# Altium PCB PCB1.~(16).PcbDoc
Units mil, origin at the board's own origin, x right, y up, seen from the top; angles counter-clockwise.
Board outline 1890 x 1900 mil, 2 copper layers (Top Layer, Bottom Layer); 27 components, 29 nets, 115 pads, 18 vias.
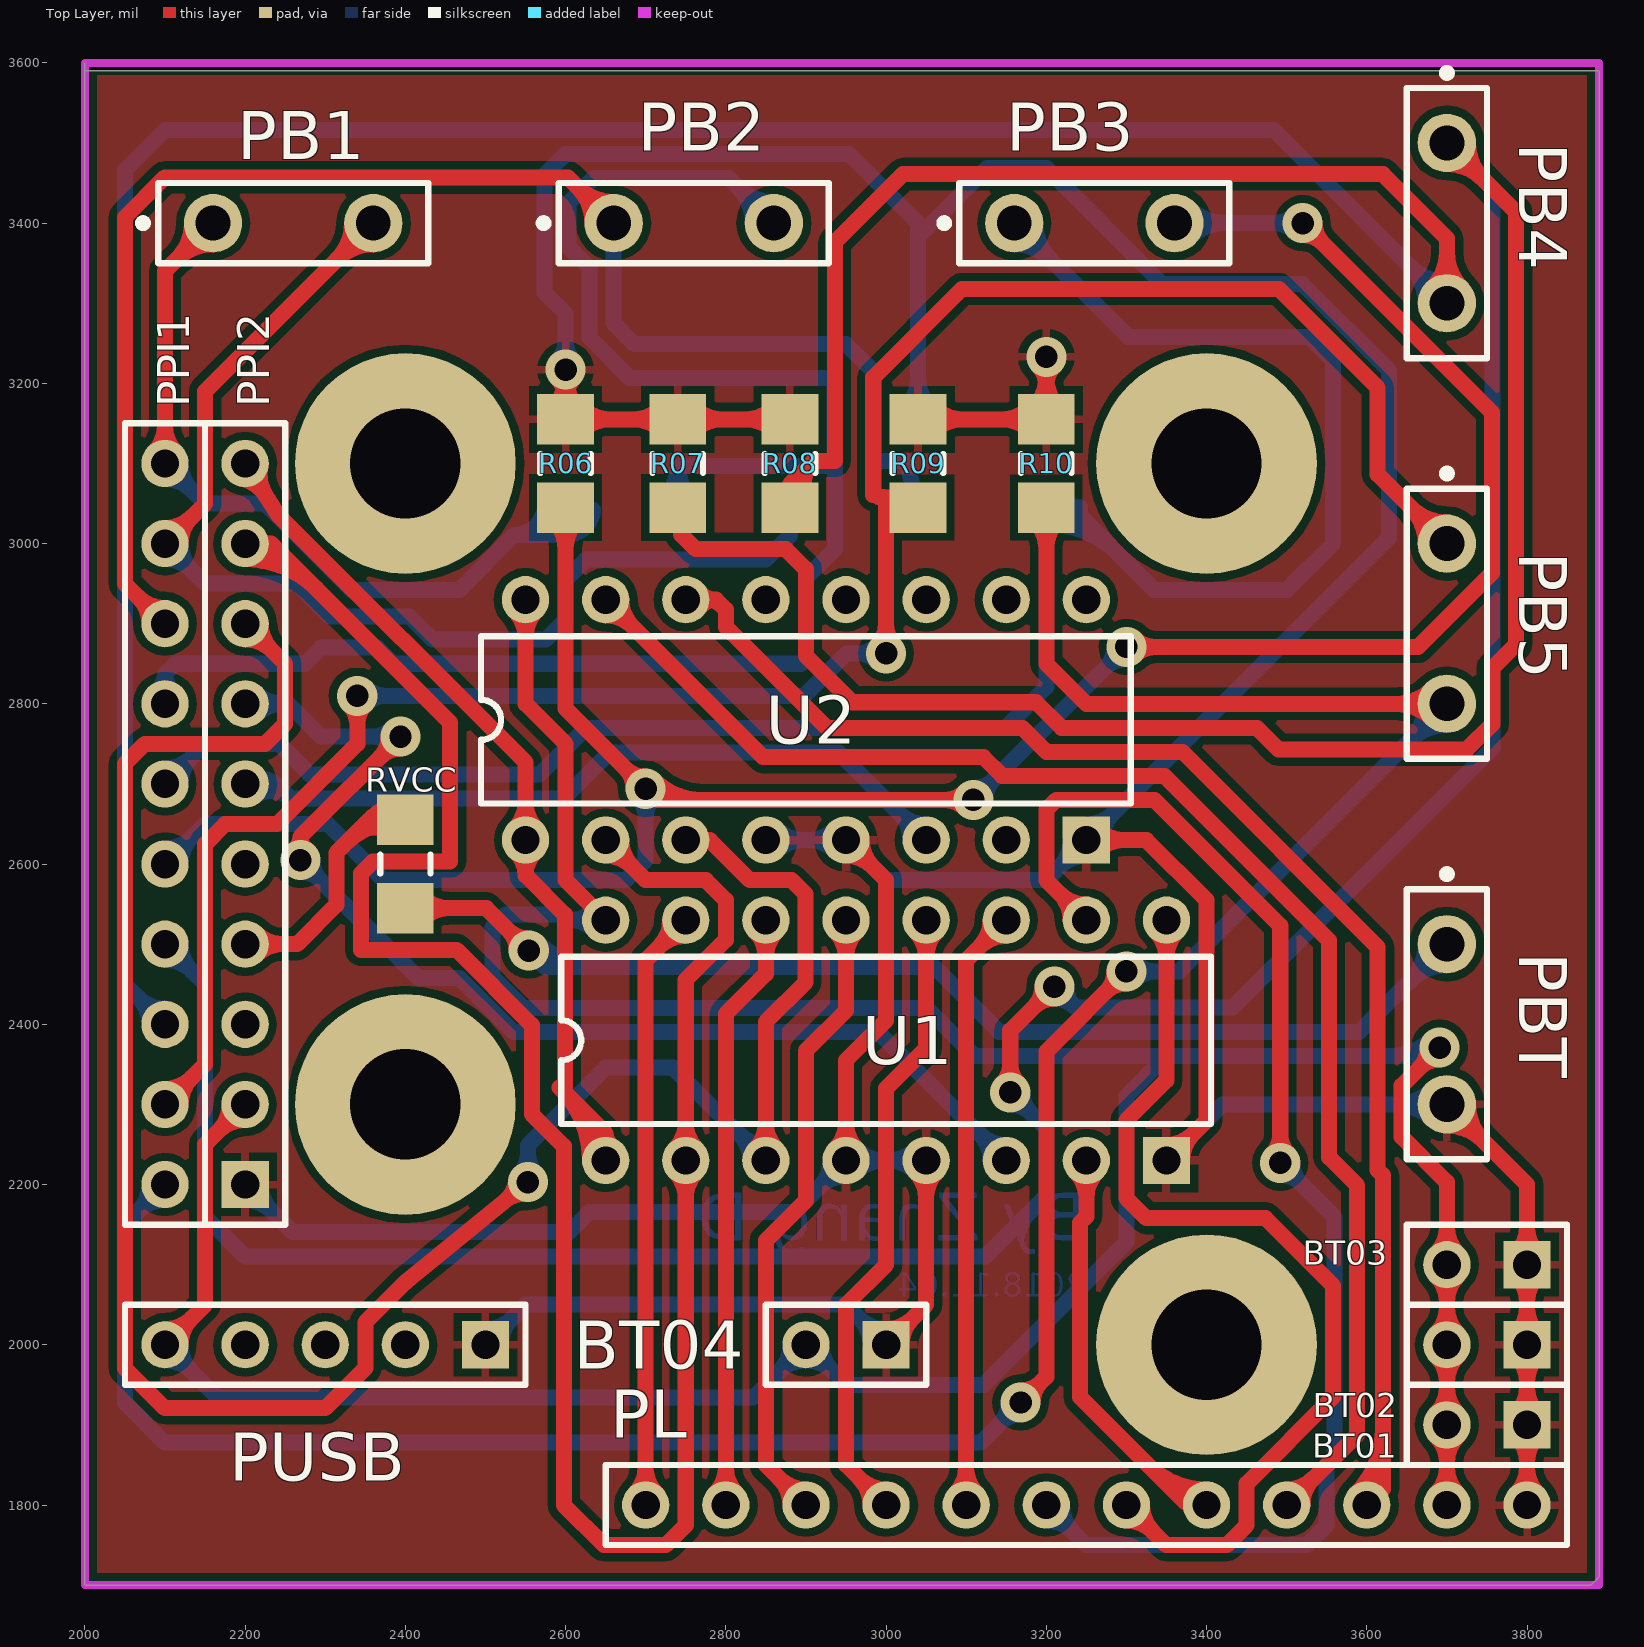
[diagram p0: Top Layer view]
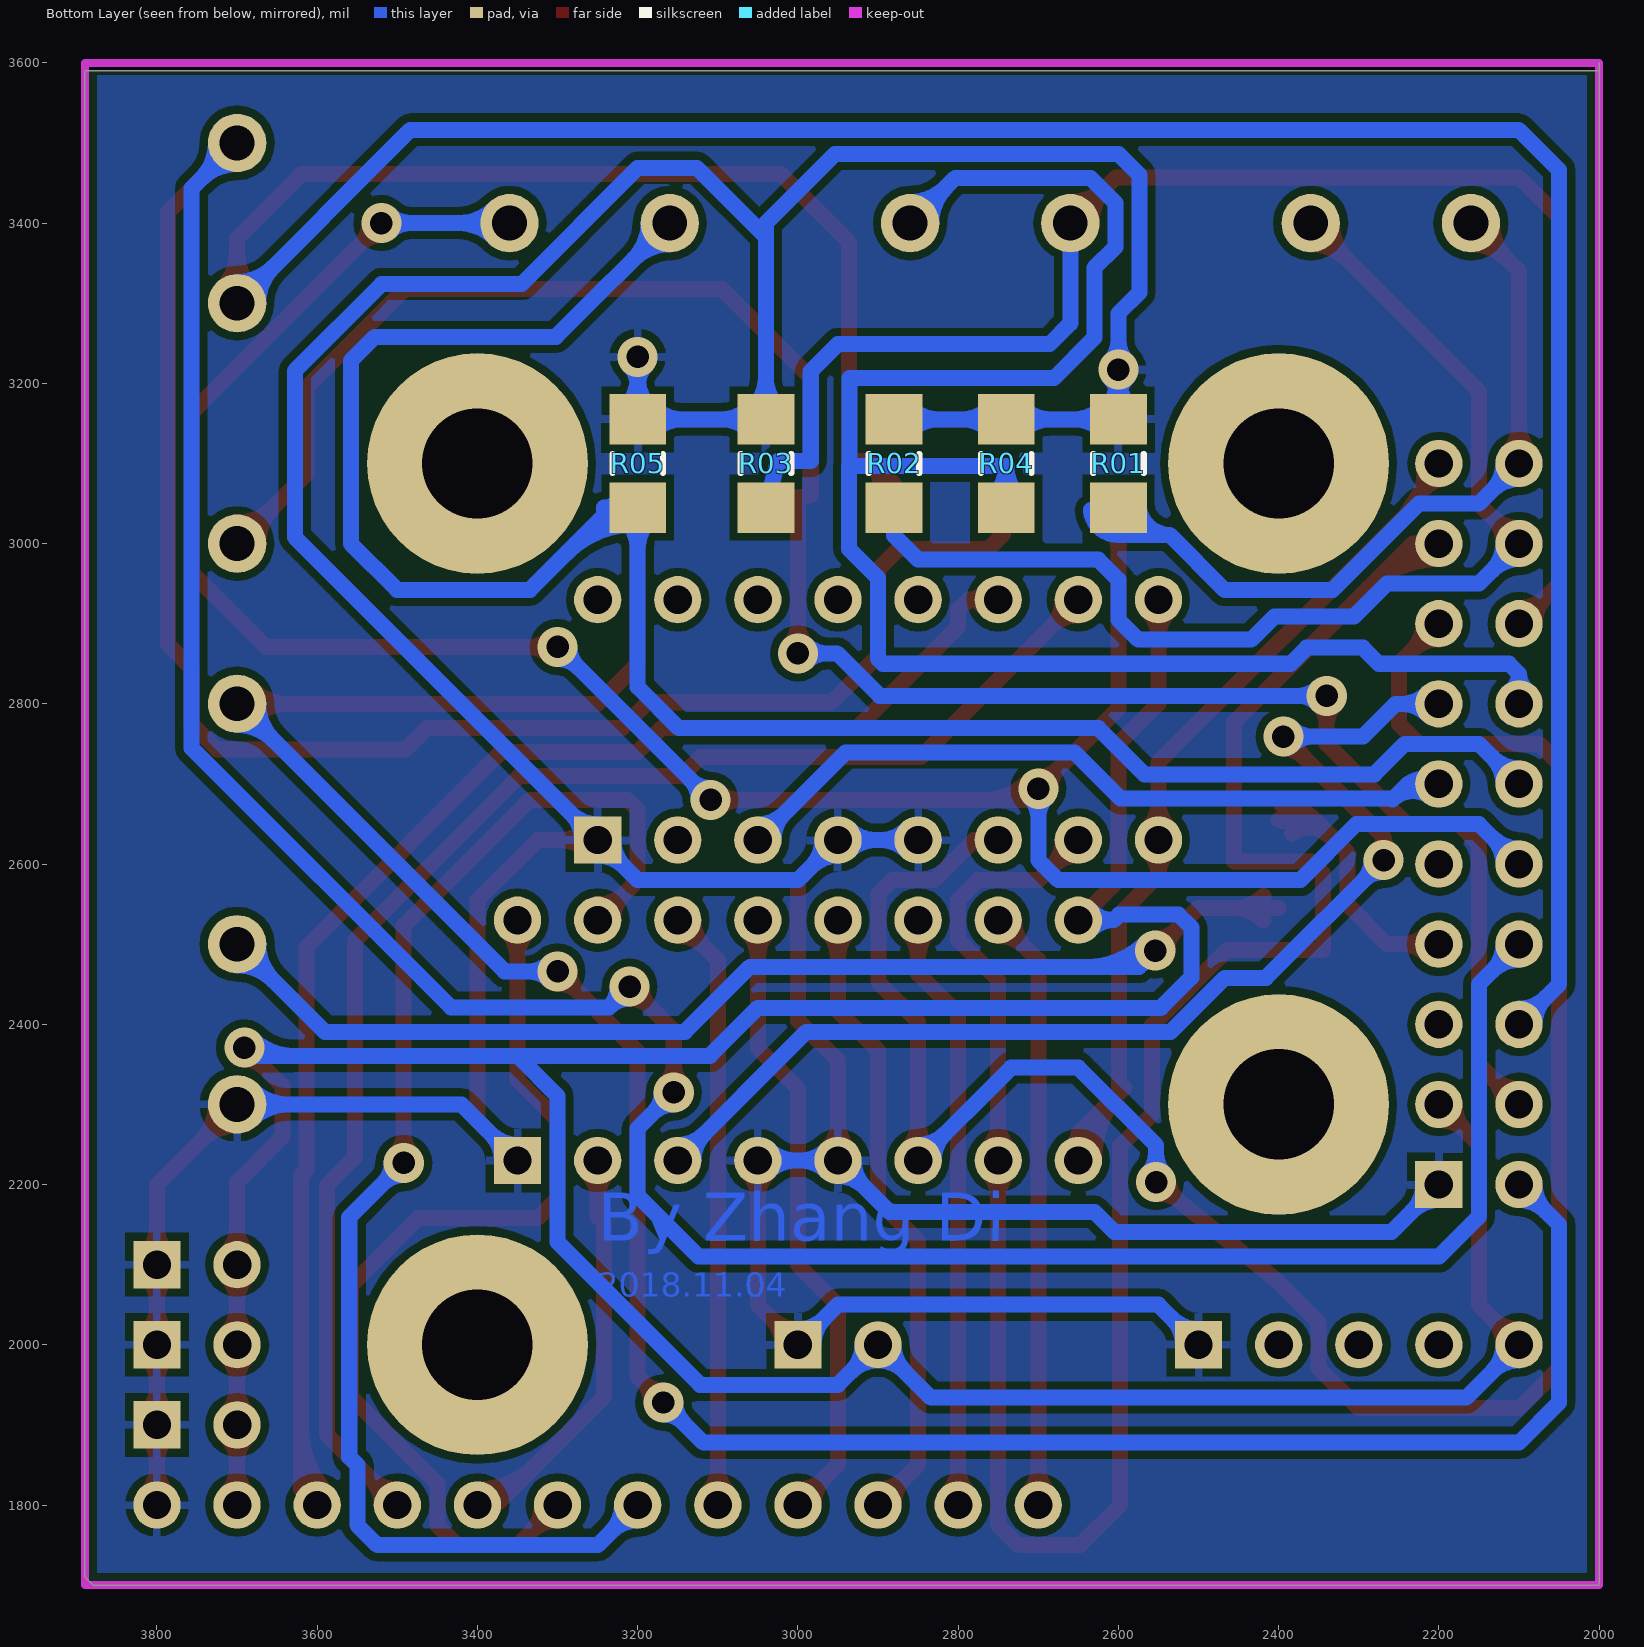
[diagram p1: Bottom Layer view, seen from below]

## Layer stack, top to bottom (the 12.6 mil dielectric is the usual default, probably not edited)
Top Layer: signal copper 1.4
Dielectric: dielectric 12.6, FR-4, Dk 4.8
Bottom Layer: signal copper 1.4

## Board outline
2010,3590 3890,3590 3890,1710 3880,1700 2000,1700 2000,3600 2000,3590

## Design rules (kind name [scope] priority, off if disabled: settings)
Clearance [All] p1: gap=10
ComponentClearance [All] p1: gap=10 collisioncheckmode=3 verticalgap=10
PolygonConnect [All] p1: connectstyle=Relief reliefconductorwidth=10 reliefentries=4 polygonreliefangle="90 Angle"
RoomDefinition Sheet1 [InComponentClass('Sheet1')] p1: confinementstyle=ConfineIn formatcopy=TRUE lockcomponents=FALSE outline 0,0 2000,0 2000,1000 0,1000
RoutingVias [All] p1: holewidth=28 width=50 viastyle="Through Hole" minholewidth=28 minwidth=50 maxholewidth=28 maxwidth=50
SolderMaskExpansion [All] p1: expansion=4
TestPointUsage [All] p1: valid=0 allowmultiple=FALSE
Testpoint [All] p1: side=15 testpointundercomponent=TRUE minsize=40 maxsize=100 preferedsize=60 minholesize=0 maxholesize=40 preferedholesize=32 testpointgrid=1 style=1023 order=0123456789
Width Width_2 [All] p1: maxlimit=30 minlimit=15 preferedwidth=20
Width Width_1 [InNet('VCC')] p2: maxlimit=30 minlimit=20 preferedwidth=30
Width [InNet('GND')] p3: maxlimit=30 minlimit=20 preferedwidth=30
18 further rules are at their usual default settings.

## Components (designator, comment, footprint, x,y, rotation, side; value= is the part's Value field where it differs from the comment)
BT01 "Header 2" HDR1X2 3800,1900 r180 top
BT02 "Header 2" HDR1X2 3800,2000 r180 top
BT03 "Header 2" HDR1X2 3800,2100 r180 top
BT04 "Header 2" HDR1X2 3000,2000 r180 top
PB1 "Header 2" SPST-2 2260,3400 r0 top
PB2 "Header 2" SPST-2 2760,3400 r0 top
PB3 "Header 2" SPST-2 3260,3400 r0 top
PB4 "Header 2" SPST-2 3700,3400 r270 top
PB5 "Header 2" SPST-2 3700,2900 r270 top
PBT "Header 2" SPST-2 3700,2400 r270 top
PL "Header 12" HDR1X12 2700,1800 r0 top
PPI1 "Header 10" HDR1X10#1 2100,3100 r270 top
PPI2 "Header 10" HDR1X10#2 2200,3100 r270 top
PUSB "Header 5" HDR1X5 2100,2000 r0 top
R01 "Res1" 3216[1206] 2600,3100 r270 bottom
R02 "Res1" 3216[1206] 2880,3100 r270 bottom
R03 "Res1" 3216[1206] 3040,3100 r270 bottom
R04 "Res1" 3216[1206] 2740,3100 r270 bottom
R05 "Res1" 3216[1206] 3200,3100 r270 bottom
R06 "Res1" 3216[1206] 2600,3100 r270 top
R07 "Res1" 3216[1206] 2740,3100 r270 top
R08 "Res1" 3216[1206] 2880,3100 r270 top
R09 "Res1" 3216[1206] 3040,3100 r270 top
R10 "Res1" 3216[1206] 3200,3100 r270 top
RVCC "Res1" 3216[1206] 2400,2600 r90 top
U1 "SN74HC138D" DIP-16 3000,2380 r0 top
U2 "SN74HC138D" DIP-16 2900,2780 r0 top

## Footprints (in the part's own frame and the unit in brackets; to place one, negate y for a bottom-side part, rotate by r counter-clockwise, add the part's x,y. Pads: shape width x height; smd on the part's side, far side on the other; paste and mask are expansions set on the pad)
3216[1206] [mm] "Chip Resistor; Body 3.2 x 1.6 mm (LxW typ)"
  rect 1.6x1.8 smd: 1(-1.4,0) 2(1.4,0)
  silkscreen extent -0.3,-0.8 0.3,0.8
DIP-16 [mm] "DIP; 16 Leads; Row Spacing 7.62 mm; Pitch 2.54 mm"
  round 1.5 hole 0.9: 1(-8.89,-3.81) 2(-6.35,-3.81) 3(-3.81,-3.81) 4(-1.27,-3.81) 5(1.27,-3.81) 6(3.81,-3.81) 7(6.35,-3.81) 9(8.89,3.81) 10(6.35,3.81) 11(3.81,3.81) 12(1.27,3.81) 13(-1.27,3.81) 14(-3.81,3.81) 15(-6.35,3.81) 16(-8.89,3.81)
  rect 1.5x1.5 hole 0.9: 8(8.89,-3.81)
  silkscreen extent -10.3,-2.65 10.3,2.65
HDR1X2 [mm] "Connector; Header; 2 Position"
  rect 1.5x1.5 hole 0.9: 1(0,0)
  round 1.5 hole 0.9: 2(2.54,0)
  silkscreen extent -1.27,-1.27 3.81,1.27
HDR1X5 [mm] "Connector; Header; 5 Position"
  round 1.5 hole 0.9: 1(0,0) 2(2.54,0) 3(5.08,0) 4(7.62,0)
  rect 1.5x1.5 hole 0.9: 5(10.16,0)
  silkscreen extent -1.27,-1.27 11.43,1.27
HDR1X10#1 [mm] "Connector; Header; 10 Position"
  round 1.5 hole 0.9: 1(0,0) 2(2.54,0) 3(5.08,0) 4(7.62,0) 5(10.16,0) 6(12.7,0) 7(15.24,0) 8(17.78,0) 9(20.32,0) 10(22.86,0)
  silkscreen extent -1.27,-1.27 24.13,1.27
HDR1X10#2 [mm] "Connector; Header; 10 Position"
  round 1.5 hole 0.9: 1(0,0) 2(2.54,0) 3(5.08,0) 4(7.62,0) 5(10.16,0) 6(12.7,0) 7(15.24,0) 8(17.78,0) 9(20.32,0)
  rect 1.5x1.5 hole 0.9: 10(22.86,0)
  silkscreen extent -1.27,-1.27 24.13,1.27
HDR1X12 [mm] "Connector; Header; 12 Position"
  round 1.5 hole 0.9: 1(0,0) 2(2.54,0) 3(5.08,0) 4(7.62,0) 5(10.16,0) 6(12.7,0) 7(15.24,0) 8(17.78,0) 9(20.32,0) 10(22.86,0) 11(25.4,0) 12(27.94,0)
  silkscreen extent -1.27,-1.27 29.21,1.27
SPST-2 [mm] "Circuit Breaker; 2 Leads"
  round 1.85 hole 1.1: 1(-2.54,0) 2(2.54,0)
  silkscreen extent -4.89,-1.27 4.28,1.27

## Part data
BT01 BT02 BT03 BT04 PB1 PB2 PB3 PB4 PB5 PBT: "Header, 2-Pin"
PL: "Header, 12-Pin"
PPI1 PPI2: "Header, 10-Pin"
PUSB: "Header, 5-Pin"
R01 R02 R03 R04 R05 R06 R07 R08 R09 R10 RVCC: "Resistor"
U1 U2: "3-Line to 8-Line Decoder / Demultiplexer"

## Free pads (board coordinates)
  round 275.59 hole 137.8: 0(3400,3100) 1(2400,3100) 3(3400,2000)
  round 275.59 hole 137.8 paste+0: 2(2400,2300)

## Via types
v1: diameter 50, hole 28, Top Layer to Bottom Layer, 18 vias

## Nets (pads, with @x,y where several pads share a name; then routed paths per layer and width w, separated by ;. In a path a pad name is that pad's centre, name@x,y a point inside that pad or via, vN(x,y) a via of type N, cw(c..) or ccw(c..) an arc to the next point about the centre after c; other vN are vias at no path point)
GND: BT01.1 BT02.1 BT03.1 BT04.1 PBT.2 PL.12 PPI2.10 PUSB.5 R01.1 R02.1 R03.1 R04.1 R05.1 R06.1 R07.1 R08.1 R09.1 R10.1 U1.4 U1.5 U1.8 U2.4 U2.5 U2.8 | length 11397.6
  Top Layer w20: R06.1@2584.8,3170.32 ccw(c2548.1,3207.01) 2600,3207.01 ccw(c2651.9,3207.01) R06.1@2615.2,3170.32 ; v1@2589.39,3206.39 cw(c2563.79,3180.79) 2600,3180.79 cw(c2636.21,3180.79) v1@2610.61,3206.39 ; v1(2600,3217) R06.1 R07.1 R08.1 ; R06.1@2619.14,3139.92 cw(c2655.83,3103.22) 2655.83,3155.12 cw(c2655.83,3207.01) R06.1@2619.14,3170.32 ; R07.1@2720.86,3139.92 ccw(c2684.17,3103.22) 2684.17,3155.12 ccw(c2684.17,3207.01) R07.1@2720.86,3170.32 ; R07.1@2759.14,3139.92 cw(c2795.83,3103.22) 2795.83,3155.12 cw(c2795.83,3207.01) R07.1@2759.14,3170.32 ; R08.1@2860.86,3139.92 ccw(c2824.17,3103.22) 2824.17,3155.12 ccw(c2824.17,3207.01) R08.1@2860.86,3170.32 ; U1.4@2936.19,2243.81 ccw(c2902.86,2277.14) 2950,2277.14 ccw(c2997.14,2277.14) U1.4@2963.81,2243.81 ; U1.4 2950,2355 3000,2405 3000,2580 U2.5 ; U2.5@2950,2610.47 cw(c2950,2563.33) 2983.34,2596.66 cw(c3016.67,2630) U2.5@2969.53,2630 ; BT04.1 3050,2050 U1.5 ; BT04.1@3000,2019.53 ccw(c3000,2066.67) 3033.34,2033.34 ccw(c3066.67,2000) BT04.1@3019.53,2000 ; U1.5@3036.19,2216.19 cw(c3002.86,2182.86) 3050,2182.86 cw(c3097.14,2182.86) U1.5@3063.81,2216.19 ; R09.1 R10.1 v1(3200,3233) ; R09.1@3059.14,3139.92 cw(c3095.83,3103.22) 3095.83,3155.12 cw(c3095.83,3207.01) R09.1@3059.14,3170.32 ; R10.1@3180.86,3139.92 ccw(c3144.17,3103.22) 3144.17,3155.12 ccw(c3144.17,3207.01) R10.1@3180.86,3170.32 ; R10.1@3184.8,3170.32 ccw(c3148.1,3207.01) 3200,3207.01 ccw(c3251.9,3207.01) R10.1@3215.2,3170.32 ; v1@3189.39,3222.39 cw(c3163.79,3196.79) 3200,3196.79 cw(c3236.21,3196.79) v1@3210.61,3222.39 ; U2.8 3325,2630 3400,2555 3400,2280 U1.8 ; U2.8@3263.81,2616.19 cw(c3297.14,2582.86) 3297.14,2630 cw(c3297.14,2677.14) U2.8@3263.81,2643.81 ; U1.8@3350,2249.53 ccw(c3350,2296.67) 3383.34,2263.34 ccw(c3416.67,2230) U1.8@3369.53,2230 ; PBT.2@3700,2273.58 cw(c3700,2209.81) 3745.1,2254.9 cw(c3790.19,2300) PBT.2@3726.42,2300 ; PBT.2 3800,2200 BT03.1 BT02.1 BT01.1 PL.12 ; PL.12@3786.19,1813.81 ccw(c3752.86,1847.14) 3800,1847.14 ccw(c3847.14,1847.14) PL.12@3813.81,1813.81 ; BT01.1@3786.19,1886.19 cw(c3752.86,1852.86) 3800,1852.86 cw(c3847.14,1852.86) BT01.1@3813.81,1886.19 ; BT01.1@3786.19,1913.81 ccw(c3752.86,1947.14) 3800,1947.14 ccw(c3847.14,1947.14) BT01.1@3813.81,1913.81 ; BT02.1@3786.19,1986.19 cw(c3752.86,1952.86) 3800,1952.86 cw(c3847.14,1952.86) BT02.1@3813.81,1986.19 ; BT02.1@3786.19,2013.81 ccw(c3752.86,2047.14) 3800,2047.14 ccw(c3847.14,2047.14) BT02.1@3813.81,2013.81 ; BT03.1@3786.19,2086.19 cw(c3752.86,2052.86) 3800,2052.86 cw(c3847.14,2052.86) BT03.1@3813.81,2086.19 ; BT03.1@3786.19,2113.81 ccw(c3752.86,2147.14) 3800,2147.14 ccw(c3847.14,2147.14) BT03.1@3813.81,2113.81
  Bottom Layer w20: PPI2.10@2200,2180.47 cw(c2200,2133.33) 2233.34,2166.66 cw(c2266.67,2200) PPI2.10@2219.53,2200 ; PPI2.10 2259,2141 2605,2141 2630,2166 2886,2166 U1.4 U1.5 ; PUSB.5 2550,2050 2950,2050 BT04.1 ; PUSB.5@2500,2019.53 ccw(c2500,2066.67) 2533.34,2033.34 ccw(c2566.67,2000) PUSB.5@2519.53,2000 ; R01.1@2584.8,3170.32 ccw(c2548.1,3207.01) 2600,3207.01 ccw(c2651.9,3207.01) R01.1@2615.2,3170.32 ; v1@2589.39,3206.39 cw(c2563.79,3180.79) 2600,3180.79 cw(c2636.21,3180.79) v1@2610.61,3206.39 ; v1@2589.39,3227.61 ccw(c2563.79,3253.21) 2600,3253.21 ccw(c2636.21,3253.21) v1@2610.61,3227.61 ; R01.1@2619.14,3139.92 cw(c2655.83,3103.22) 2655.83,3155.12 cw(c2655.83,3207.01) R01.1@2619.14,3170.32 ; R04.1@2720.86,3139.92 ccw(c2684.17,3103.22) 2684.17,3155.12 ccw(c2684.17,3207.01) R04.1@2720.86,3170.32 ; R04.1@2759.14,3139.92 cw(c2795.83,3103.22) 2795.83,3155.12 cw(c2795.83,3207.01) R04.1@2759.14,3170.32 ; U2.4 U2.5 3000,2580 3200,2580 U2.8 3628,3008 3628,3215.5 3519.5,3324 3345,3324 3200,3469 3126,3469 3040,3383 ; R02.1@2860.86,3139.92 ccw(c2824.17,3103.22) 2824.17,3155.12 ccw(c2824.17,3207.01) R02.1@2860.86,3170.32 ; U2.4@2863.81,2616.19 cw(c2897.14,2582.86) 2897.14,2630 cw(c2897.14,2677.14) U2.4@2863.81,2643.81 ; R02.1 R04.1 R01.1 v1(2600,3217) 2600,3287.16 2573.58,3313.58 2573.58,3460 2600,3486.42 2953.58,3486.42 3040,3400 3040,3383 ; U1.4@2930.47,2230 cw(c2883.33,2230) 2916.66,2196.66 cw(c2950,2163.33) U1.4@2950,2210.47 ; U2.5@2936.19,2616.19 ccw(c2902.86,2582.86) 2902.86,2630 ccw(c2902.86,2677.14) U2.5@2936.19,2643.81 ; U2.5@2950,2610.47 cw(c2950,2563.33) 2983.34,2596.66 cw(c3016.67,2630) U2.5@2969.53,2630 ; U1.4@2963.81,2216.19 cw(c2997.14,2182.86) 2997.14,2230 cw(c2997.14,2277.14) U1.4@2963.81,2243.81 ; BT04.1@2980.47,2000 ccw(c2933.33,2000) 2966.66,2033.34 ccw(c3000,2066.67) BT04.1@3000,2019.53 ; R03.1@3024.8,3170.32 ccw(c2988.1,3207.01) 3040,3207.01 ccw(c3091.9,3207.01) R03.1@3055.2,3170.32 ; U1.5@3036.19,2216.19 ccw(c3002.86,2182.86) 3002.86,2230 ccw(c3002.86,2277.14) U1.5@3036.19,2243.81 ; R03.1@3059.14,3139.92 cw(c3095.83,3103.22) 3095.83,3155.12 cw(c3095.83,3207.01) R03.1@3059.14,3170.32 ; R05.1@3180.86,3139.92 ccw(c3144.17,3103.22) 3144.17,3155.12 ccw(c3144.17,3207.01) R05.1@3180.86,3170.32 ; R05.1@3184.8,3170.32 ccw(c3148.1,3207.01) 3200,3207.01 ccw(c3251.9,3207.01) R05.1@3215.2,3170.32 ; v1@3189.39,3222.39 cw(c3163.79,3196.79) 3200,3196.79 cw(c3236.21,3196.79) v1@3210.61,3222.39 ; v1(3200,3233) R05.1 R03.1 3040,3383 ; U2.8@3230.47,2630 cw(c3183.33,2630) 3216.66,2596.66 cw(c3250,2563.33) U2.8@3250,2610.47 ; U2.8@3250,2649.53 ccw(c3250,2696.67) 3283.34,2663.34 ccw(c3316.67,2630) U2.8@3269.53,2630 ; U1.8 3420,2300 PBT.2 ; U1.8@3350,2249.53 ccw(c3350,2296.67) 3383.34,2263.34 ccw(c3416.67,2230) U1.8@3369.53,2230 ; PBT.2@3681.32,2281.32 ccw(c3636.22,2236.22) 3636.22,2300 ccw(c3636.22,2363.78) PBT.2@3681.32,2318.68
NetPB1_1: PB1.1 PPI1.1 R01.2 | length 1416.3
  Top Layer w20: PPI1.1@2086.19,3113.81 ccw(c2052.86,3147.14) 2100,3147.14 ccw(c2147.14,3147.14) PPI1.1@2113.81,3113.81 ; PPI1.1 2100,3340 PB1.1 ; PB1.1@2133.58,3400 cw(c2069.81,3400) 2114.9,3354.9 cw(c2160,3309.81) PB1.1@2160,3373.58
  Bottom Layer w20: PPI1.1@2100,3080.47 cw(c2100,3033.33) 2133.34,3066.66 cw(c2166.67,3100) PPI1.1@2119.53,3100 ; PPI1.1 2150,3050 2225,3050 2333,2942 2467,2942 2536,3011 ; 2557.69,3011 ccw(c2557.69,3048) R01.2@2594.57,3045 ; R01.2@2574.64,3046.62 cw(c2536,3049.76) 2536,3011 ; 2579.38,3011 ccw(c2579.38,3046.24) R01.2@2614.51,3043.38 ; R01.2 2600,3011 2536,3011 ; 2601.08,3011 ccw(c2601.08,3044.47) R01.2@2634.44,3041.76
NetPB1_2: PB1.2 PPI1.2 R02.2 | length 1703.7
  Top Layer w20: PPI1.2 2150,3050 2150,3190 PB1.2 ; PPI1.2@2100,3019.53 ccw(c2100,3066.67) 2133.34,3033.34 ccw(c2166.67,3000) PPI1.2@2119.53,3000 ; PB1.2@2333.58,3400 cw(c2269.81,3400) 2314.9,3354.9 cw(c2360,3309.81) PB1.2@2360,3373.58
  Bottom Layer w20: PPI1.2@2100,2980.47 cw(c2100,2933.33) 2133.34,2966.66 cw(c2166.67,3000) PPI1.2@2119.53,3000 ; PPI1.2 2150,2950 2264.98,2950 2306.05,2908.93 2405.3,2908.93 2434.23,2880 2575,2880 2600,2905 2600,2955 2625,2980 2850,2980 2880,3010 R02.2
NetPB2_1: PB2.1 PPI1.3 R03.2 | length 2043.1
  Top Layer w20: PPI1.3@2080.47,2900 ccw(c2033.33,2900) 2066.66,2933.34 ccw(c2100,2966.67) PPI1.3@2100,2919.53 ; PPI1.3 2050,2950 2050,3407 2100,3457 2603,3457 PB2.1 ; PB2.1@2633.58,3400 ccw(c2569.81,3400) 2614.9,3445.1 ccw(c2660,3490.19) PB2.1@2660,3426.42
  Bottom Layer w20: PB2.1 2660,3275 2686,3249 2950,3249 2984,3215 2984,3103 3025,3103 R03.2
NetPB2_2: PB2.2 PPI1.4 R04.2 | length 2505.4
  Bottom Layer w20: PPI1.4@2088.8,2816 ccw(c2073.76,2837.5) 2100,2837.5 ; PPI1.4 2100,2837.5 ; PPI1.4@2111.2,2816 cw(c2126.24,2837.5) 2100,2837.5 ; R04.2@2724.8,3060.08 ccw(c2688.1,3096.78) 2740,3096.78 ccw(c2791.9,3096.78) R04.2@2755.2,3060.08 ; R04.2 2740,3097 2935.44,3097 ; PB2.2@2833.58,3400 ccw(c2769.81,3400) 2814.9,3445.1 ccw(c2860,3490.19) PB2.2@2860,3426.42 ; PB2.2 2803.58,3456.42 2635,3456.42 2603.58,3425 2603.58,3370.42 2630,3344 2630,3257 2680.38,3206.62 2935.44,3206.62 2935.44,3097 ; 2100,2837.5 2112.5,2850 2275,2850 2295,2870 2365,2870 2385,2850 2893.74,2850 2900,2856.26 2900,2957 2936,2993 2936,3097 2935.44,3097
NetPB3_1: PB3.1 PPI1.5 R05.2 | length 3067.5
  Bottom Layer w20: PPI1.5 2150,2750 2242.5,2750 2280.5,2712 2567.47,2712 2625,2769.53 3148.53,2769.53 3200,2821 R05.2 3242.2,3044.88 ; PPI1.5@2100,2719.53 ccw(c2100,2766.67) 2133.34,2733.34 ccw(c2166.67,2700) PPI1.5@2119.53,2700 ; PB3.1@3160,3373.58 cw(c3160,3309.81) 3205.1,3354.9 cw(c3250.19,3400) PB3.1@3186.42,3400 ; PB3.1 3302,3258 3528,3258 3558,3228 3558,3000 3500.2,2942.2 3334.64,2942.2 3242.2,3034.64 3242.2,3044.88 ; R05.2@3184.8,3029.68 cw(c3148.1,2992.99) 3200,2992.99 cw(c3251.9,2992.99) R05.2@3215.2,3029.68 ; R05.2@3203.94,3023.39 cw(c3203.94,2903.84) 3288.47,2988.37 ; R05.2@3203.94,3043.39 cw(c3203.94,2972.12) 3254.33,3022.51 ; R05.2@3204.68,3043.58 cw(c3218.28,3019.75) 3237.69,3039.15 ; R05.2@3214.59,3026.21 cw(c3231.75,2996.16) 3256.21,3020.63 ; R05.2@3222.29,3033.7 cw(c3242.2,3021.57) 3242.2,3044.88 ; R05.2@3222.29,3056.07 ccw(c3242.2,3068.19) 3242.2,3044.88
NetPB3_2: PB3.2 PPI1.6 R06.2 | length 3820.4
  Top Layer w20: R06.2@2584.8,3029.68 cw(c2548.1,2992.99) 2600,2992.99 cw(c2651.9,2992.99) R06.2@2615.2,3029.68 ; R06.2 2600,2794 v1(2700,2694) 2714,2680 v1(3109,2680) ; v1@2685,2694 ccw(c2648.79,2694) 2674.39,2719.61 ccw(c2700,2745.21) v1@2700,2709 ; v1@2696.46,2690.46 ccw(c2721.73,2715.73) 2721.73,2680 ; v1@2710.61,2704.61 ccw(c2770.01,2764.01) 2770.01,2680 ; v1@3098.39,2669.39 ccw(c3072.79,2643.79) 3072.79,2680 ccw(c3072.79,2716.21) v1@3098.39,2690.61 ; v1(3300,2871) 3664,2871 3756.42,2963.42 3756.42,3163.58 v1(3520,3400) ; v1@3310.61,2860.39 cw(c3336.21,2834.79) 3336.21,2871 cw(c3336.21,2907.21) v1@3310.61,2881.61 ; v1@3520,3385 cw(c3520,3348.79) 3545.61,3374.39 cw(c3571.21,3400) v1@3535,3400
  Bottom Layer w20: PPI1.6 2150,2650 2303,2650 2373,2580 2675,2580 2700,2605 v1(2700,2694) ; PPI1.6@2100,2619.53 ccw(c2100,2666.67) 2133.34,2633.34 ccw(c2166.67,2600) PPI1.6@2119.53,2600 ; v1@2689.39,2683.39 cw(c2663.79,2657.79) 2700,2657.79 cw(c2736.21,2657.79) v1@2710.61,2683.39 ; v1(3109,2680) v1(3300,2871) ; v1@3109,2695 ccw(c3109,2731.21) 3134.61,2705.61 ccw(c3160.21,2680) v1@3124,2680 ; v1@3285,2871 cw(c3248.79,2871) 3274.39,2845.39 cw(c3300,2819.79) v1@3300,2856 ; PB3.2 v1(3520,3400) ; PB3.2@3378.68,3381.32 cw(c3423.78,3336.22) 3423.78,3400 cw(c3423.78,3463.78) PB3.2@3378.68,3418.68 ; v1@3509.39,3389.39 ccw(c3483.79,3363.79) 3483.79,3400 ccw(c3483.79,3436.21) v1@3509.39,3410.61
NetPB4_1: PB4.1 PPI1.7 R07.2 | length 5783.7
  Top Layer w20: R07.2@2735.1,3025.29 cw(c2728.87,3011.5) 2744,3011.5 ; R07.2 2744,3044.88 2744,3011.5 ; R07.2@2752.88,3025.34 ccw(c2759.22,3011.5) 2744,3011.5 ; v1@3144.39,2325.61 ccw(c3118.79,2351.21) 3155,2351.21 ccw(c3191.21,2351.21) v1@3165.61,2325.61 ; v1(3155,2315) 3155,2392 v1(3210,2447) ; v1@3195,2447 cw(c3158.79,2447) 3184.39,2421.39 cw(c3210,2395.79) v1@3210,2432 ; PB4.1@3700,3473.58 cw(c3700,3409.81) 3745.1,3454.9 cw(c3790.19,3500) PB4.1@3726.42,3500 ; PB4.1 3786.42,3413.58 3786.42,2874.48 3757,2845.06 3757,2775 3725,2743 3489.71,2743 3462.71,2770 3219.08,2770 3187.13,2801.95 2958.05,2801.95 2900,2860 2900,2968 2875,2993 2762.5,2993 2744,3011.5
  Bottom Layer w20: PPI1.7@2100,2480.47 cw(c2100,2433.33) 2133.34,2466.66 cw(c2166.67,2500) PPI1.7@2119.53,2500 ; PPI1.7 2150,2450 2150,2160 2200,2110 3124,2110 3200,2186 3200,2270 v1(3155,2315) ; v1@3155,2300 cw(c3155,2263.79) 3180.61,2289.39 cw(c3206.21,2315) v1@3170,2315 ; v1@3210,2432 cw(c3210,2395.79) 3235.61,2421.39 cw(c3261.21,2447) v1@3225,2447 ; v1(3210,2447) 3236,2421 3433,2421 3757,2745 3757,3443 PB4.1 ; PB4.1@3700,3473.58 cw(c3700,3409.81) 3745.1,3454.9 cw(c3790.19,3500) PB4.1@3726.42,3500
NetPB4_2: PB4.2 PPI1.8 R08.2 | length 4498.7
  Top Layer w20: R08.2 2880,3074 2909,3103 ; R08.2@2885.24,3045.62 cw(c2913.3,3061.62) 2890.46,3084.46 ; R08.2@2902.61,3055.53 cw(c2936.92,3075.08) 2909,3103 ; PB4.2@3681.32,3318.68 ccw(c3636.22,3363.78) 3700,3363.78 ccw(c3763.78,3363.78) PB4.2@3718.68,3318.68 ; PB4.2 3700,3381 3620,3461 3021,3461 2936,3376 2936,3103 2909,3103
  Bottom Layer w20: PPI1.8@2080.47,2400 ccw(c2033.33,2400) 2066.66,2433.34 ccw(c2100,2466.67) PPI1.8@2100,2419.53 ; PPI1.8 2050,2450 2050,3466 2100.42,3516.42 3483.58,3516.42 PB4.2 ; PB4.2@3673.58,3300 ccw(c3609.81,3300) 3654.9,3345.1 ccw(c3700,3390.19) PB4.2@3700,3326.42
NetPB5_1: PB5.1 PPI1.9 R09.2 | length 3237.7
  Top Layer w20: PPI1.9 2150,2350 2150,2625 2175,2650 2240,2650 2340,2750 v1(2340,2810) ; PPI1.9@2100,2319.53 ccw(c2100,2366.67) 2133.34,2333.34 ccw(c2166.67,2300) PPI1.9@2119.53,2300 ; v1@2329.39,2799.39 cw(c2303.79,2773.79) 2340,2773.79 cw(c2376.21,2773.79) v1@2350.61,2799.39 ; 2983.95,3060.9 cw(c2968.68,3007.45) R09.2@3017.27,3034.44 ; 2988.97,3059.46 ccw(c3002.21,3105.81) R09.2@3025.62,3063.67 ; v1@2989.39,2873.61 ccw(c2963.79,2899.21) 3000,2899.21 ccw(c3036.21,2899.21) v1@3010.61,2873.61 ; v1(3000,2863) 3000,3044.88 ; R09.2@3017.15,3034.66 ccw(c3000,3025.38) 3000,3044.88 ; R09.2@3017.15,3055.11 cw(c3000,3064.38) 3000,3044.88 ; PB5.1@3673.58,3000 ccw(c3609.81,3000) 3654.9,3045.1 ccw(c3700,3090.19) PB5.1@3700,3026.42 ; PB5.1 3613.58,3086.42 3613.58,3194.42 3490.2,3317.8 3094.8,3317.8 2984,3207 2984,3060.88 R09.2 3000,3044.88
  Bottom Layer w20: v1(2340,2810) 2898,2810 2951,2863 v1(3000,2863) ; v1@2350.61,2799.39 cw(c2376.21,2773.79) 2376.21,2810 cw(c2376.21,2846.21) v1@2350.61,2820.61 ; v1@2989.39,2852.39 ccw(c2963.79,2826.79) 2963.79,2863 ccw(c2963.79,2899.21) v1@2989.39,2873.61
NetPB5_2: PB5.2 PPI1.10 R10.2 | length 3882.2
  Top Layer w20: v1(3168,1928) 3200,1960 3200,2366 v1(3300,2466) ; v1@3168,1943 ccw(c3168,1979.21) 3193.61,1953.61 ccw(c3219.21,1928) v1@3183,1928 ; R10.2@3184.8,3029.68 cw(c3148.1,2992.99) 3200,2992.99 cw(c3251.9,2992.99) R10.2@3215.2,3029.68 ; R10.2 3200,2850 3250,2800 PB5.2 ; v1@3285,2466 cw(c3248.79,2466) 3274.39,2440.39 cw(c3300,2414.79) v1@3300,2451 ; PB5.2@3681.32,2781.32 ccw(c3636.22,2736.22) 3636.22,2800 ccw(c3636.22,2863.78) PB5.2@3681.32,2818.68
  Bottom Layer w20: PPI1.10@2080.47,2200 cw(c2033.33,2200) 2066.66,2166.66 cw(c2100,2133.33) PPI1.10@2100,2180.47 ; PPI1.10 2050,2150 2050,1928 2100,1878 3118,1878 v1(3168,1928) ; v1@3153,1928 cw(c3116.79,1928) 3142.39,1902.39 cw(c3168,1876.79) v1@3168,1913 ; v1(3300,2466) 3366,2466 PB5.2 ; v1@3310.61,2455.39 cw(c3336.21,2429.79) 3336.21,2466 cw(c3336.21,2502.21) v1@3310.61,2476.61 ; PB5.2@3673.58,2800 cw(c3609.81,2800) 3654.9,2754.9 cw(c3700,2709.81) PB5.2@3700,2773.58
NetPBT_1: PBT.1 RVCC.1 | length 1776.3
  Top Layer w20: RVCC.1 2501.12,2544.88 v1(2554,2492) ; RVCC.1@2419.14,2529.68 cw(c2455.83,2492.99) 2455.83,2544.88 cw(c2455.83,2596.78) RVCC.1@2419.14,2560.08 ; v1@2539,2492 ccw(c2502.79,2492) 2528.39,2517.61 ccw(c2554,2543.21) v1@2554,2507
  Bottom Layer w20: v1@2550.46,2488.46 ccw(c2591.19,2529.19) 2591.19,2471.59 ; v1(2554,2492) 2574.41,2471.59 3060.09,2471.59 3141.21,2390.47 3590.47,2390.47 PBT.1 ; v1@2564.61,2502.61 ccw(c2639.48,2577.48) 2639.48,2471.59 ; PBT.1@3673.58,2500 cw(c3609.81,2500) 3654.9,2454.9 cw(c3700,2409.81) PBT.1@3700,2473.58
NetPL_1: PL.1 U1.15 | length 898.8
  Top Layer w20: PL.1@2686.19,1813.81 ccw(c2652.86,1847.14) 2700,1847.14 ccw(c2747.14,1847.14) PL.1@2713.81,1813.81 ; PL.1 2700,2480 U1.15 ; U1.15@2730.47,2530 cw(c2683.33,2530) 2716.66,2496.66 cw(c2750,2463.33) U1.15@2750,2510.47
NetPL_2: PL.2 U1.14 | length 898.8
  Top Layer w20: PL.2@2786.19,1813.81 ccw(c2752.86,1847.14) 2800,1847.14 ccw(c2847.14,1847.14) PL.2@2813.81,1813.81 ; PL.2 2800,2413 2850,2463 U1.14 ; U1.14@2836.19,2516.19 cw(c2802.86,2482.86) 2850,2482.86 cw(c2897.14,2482.86) U1.14@2863.81,2516.19
NetPL_3: PL.3 U1.13 | length 940.2
  Top Layer w20: PL.3@2880.47,1800 ccw(c2833.33,1800) 2866.66,1833.34 ccw(c2900,1866.67) PL.3@2900,1819.53 ; PL.3 2850,1850 2850,2130 2900,2180 2900,2367 2950,2417 U1.13 ; U1.13@2936.19,2516.19 cw(c2902.86,2482.86) 2950,2482.86 cw(c2997.14,2482.86) U1.13@2963.81,2516.19
NetPL_4: PL.4 U1.12 | length 940.2
  Top Layer w20: PL.4@2980.47,1800 ccw(c2933.33,1800) 2966.66,1833.34 ccw(c3000,1866.67) PL.4@3000,1819.53 ; PL.4 2950,1850 2950,2050 3000,2100 3000,2320 3050,2370 U1.12 ; U1.12@3036.19,2516.19 cw(c3002.86,2482.86) 3050,2482.86 cw(c3097.14,2482.86) U1.12@3063.81,2516.19
NetPL_5: PL.5 U1.11 | length 898.8
  Top Layer w20: PL.5@3086.19,1813.81 ccw(c3052.86,1847.14) 3100,1847.14 ccw(c3147.14,1847.14) PL.5@3113.81,1813.81 ; PL.5 3100,2480 U1.11 ; U1.11@3130.47,2530 cw(c3083.33,2530) 3116.66,2496.66 cw(c3150,2463.33) U1.11@3150,2510.47
NetPL_6: PL.6 U1.10 | length 1943.7
  Top Layer w20: U1.10@3230.47,2530 ccw(c3183.33,2530) 3216.66,2563.34 ccw(c3250,2596.67) U1.10@3250,2549.53 ; U1.10 3200,2580 3200,2667.5 3212.5,2680 3335,2680 3492,2523 v1(3492,2227) ; v1@3481.39,2237.61 ccw(c3455.79,2263.21) 3492,2263.21 ccw(c3528.21,2263.21) v1@3502.61,2237.61
  Bottom Layer w20: PL.6@3200,1780.47 cw(c3200,1733.33) 3233.34,1766.66 cw(c3266.67,1800) PL.6@3219.53,1800 ; PL.6 3250,1750 3525,1750 3550,1775 3550,1850 3560,1860 3560,2159 v1(3492,2227) ; v1@3492,2212 cw(c3492,2175.79) 3517.61,2201.39 cw(c3543.21,2227) v1@3507,2227
NetPL_7: PL.7 U1.9 | length 1343.5
  Top Layer w20: PL.7@3300,1780.47 cw(c3300,1733.33) 3333.34,1766.66 cw(c3366.67,1800) PL.7@3319.53,1800 ; PL.7 3350,1750 3425,1750 3450,1775 3450,1826.84 3558,1934.84 3558,2073.6 3473.6,2158 3325,2158 3300,2183 3300,2280 3350,2330 U1.9 ; U1.9@3336.19,2516.19 cw(c3302.86,2482.86) 3350,2482.86 cw(c3397.14,2482.86) U1.9@3363.81,2516.19
NetPL_8: PL.8 U1.7 | length 712.7
  Top Layer w20: U1.7@3236.19,2216.19 cw(c3202.86,2182.86) 3250,2182.86 cw(c3297.14,2182.86) U1.7@3263.81,2216.19 ; U1.7 3250,2160 3242,2152 3242,1934.84 3372.84,1804 3400,1804 PL.8 ; 3327.13,1849.71 ccw(c3400,1922.58) PL.8@3400,1819.53 ; 3361.27,1815.57 ccw(c3400,1854.3) PL.8@3400,1799.53
NetPL_9: PL.9 U2.15 | length 1982.8
  Top Layer w20: U2.15@2650,2910.47 cw(c2650,2863.33) 2683.34,2896.66 cw(c2716.67,2930) U2.15@2669.53,2930 ; U2.15 2846.63,2733.37 3121.63,2733.37 3145,2710 3347.43,2710 3553,2504.43 3553,2234 3588,2199 3588,1888 PL.9 ; PL.9@3500,1819.53 ccw(c3500,1866.67) 3533.34,1833.34 ccw(c3566.67,1800) PL.9@3519.53,1800
NetPL_10: PL.10 U2.14 | length 2007.9
  Top Layer w20: U2.14@2749.83,2930.44 cw(c2765.77,2889.21) 2797.03,2920.47 ; U2.14 2787.5,2930 ; U2.14@2766,2918.8 cw(c2787.5,2903.76) 2787.5,2930 ; U2.14@2766,2941.2 ccw(c2787.5,2956.24) 2787.5,2930 ; PL.10@3586.19,1813.81 ccw(c3504.57,1895.43) 3620,1895.43 ; PL.10 3620,1820 3620,2211.58 3613.58,2218 3613.58,2496.42 3370,2740 3200,2740 3170.47,2769.53 2926.47,2769.53 2800,2896 2800,2917.5 2787.5,2930 ; PL.10@3600.33,1799.67 ccw(c3552.86,1847.14) 3620,1847.14
NetPPI2_1: PPI2.1 U1.1 U2.1 | length 1472
  Top Layer w20: PPI2.1@2195.89,3080.91 cw(c2185.97,3034.82) 2225.57,3060.4 cw(c2265.18,3085.97) PPI2.1@2219.09,3095.89 ; PPI2.1 2242.2,3034.64 2550,2726.84 U2.1 2550,2586 ; U2.1@2536.19,2643.81 ccw(c2502.86,2677.14) 2550,2677.14 ccw(c2597.14,2677.14) U2.1@2563.81,2643.81 ; U2.1@2536.9,2615.52 cw(c2510.2,2586) 2550,2586 ; U2.1@2563.1,2615.52 ccw(c2589.8,2586) 2550,2586 ; 2592.66,2321.28 cw(c2501.38,2230) U1.1@2630.47,2230 ; 2626.8,2287.14 cw(c2569.66,2230) U1.1@2650.47,2230 ; U1.1@2640.18,2246.88 ccw(c2630.26,2263.94) 2650,2263.94 ; U1.1 2650,2263.95 ; U1.1@2659.82,2246.88 cw(c2669.74,2263.94) 2650,2263.94 ; 2550,2586 2599,2537 2599,2314.95 2650,2263.95
NetPPI2_2: PPI2.2 U1.2 U2.2 | length 3149
  Top Layer w20: PPI2.2@2200,2980.47 cw(c2200,2854.87) 2288.82,2943.68 ; PPI2.2 2232.5,3000 2456,2776.5 2456,2603 2359.5,2603 2344.57,2588.07 2344.57,2493 2463.94,2493 2558,2398.94 2558,2288 2598,2248 2598,1800 2648,1750 2725,1750 2750,1775 U1.2 2750,2455.47 2800,2505.47 2800,2555 2775,2580 2700,2580 U2.2 ; PPI2.2@2200,3000.47 cw(c2200,2923.15) 2254.67,2977.83 ; U2.2@2650,2610.47 cw(c2650,2563.33) 2683.34,2596.66 cw(c2716.67,2630) U2.2@2669.53,2630 ; U1.2@2736.19,2216.19 cw(c2702.86,2182.86) 2750,2182.86 cw(c2797.14,2182.86) U1.2@2763.81,2216.19 ; U1.2@2736.19,2243.81 ccw(c2702.86,2277.14) 2750,2277.14 ccw(c2797.14,2277.14) U1.2@2763.81,2243.81
NetPPI2_3: PPI2.3 U1.3 U2.3 | length 3084.8
  Top Layer w20: PPI2.3@2200,2880.47 cw(c2200,2833.33) 2233.34,2866.66 cw(c2266.67,2900) PPI2.3@2219.53,2900 ; PPI2.3 2250,2850 2250,2775 2225,2750 2075,2750 2050,2725 2050,1971 2100,1921 2300,1921 2350,1971 2350,2028 2400,2078 v1(2553,2203) ; v1@2538.08,2204.5 cw(c2502.04,2208.13) 2524.96,2180.09 cw(c2547.87,2152.04) v1@2551.5,2188.08 ; U2.3 2779.96,2630 2829.96,2580 2882.03,2580 2899.53,2562.5 2899.53,2452.53 2850,2403 U1.3 ; U1.3@2836.19,2243.81 ccw(c2802.86,2277.14) 2850,2277.14 ccw(c2897.14,2277.14) U1.3@2863.81,2243.81
  Bottom Layer w20: v1@2542.39,2213.61 ccw(c2516.79,2239.21) 2553,2239.21 ccw(c2589.21,2239.21) v1@2563.61,2213.61 ; v1(2553,2203) 2553,2249 2650,2346 2734,2346 U1.3 ; U1.3@2830.47,2230 ccw(c2783.33,2230) 2816.66,2263.34 ccw(c2850,2296.67) U1.3@2850,2249.53
NetPPI2_4: PPI2.4 U1.6 | length 1811
  Top Layer w20: v1@2260.33,2617.24 ccw(c2248.47,2634) 2269,2634 ; v1(2269,2605) 2269,2634 ; v1@2277.67,2617.24 cw(c2289.53,2634) 2269,2634 ; v1@2379,2759 cw(c2342.79,2759) 2368.39,2733.39 cw(c2394,2707.79) v1@2394,2744 ; v1(2394,2759) 2269,2634
  Bottom Layer w20: PPI2.4 2254,2800 2295,2759 v1(2394,2759) ; PPI2.4@2213.81,2786.19 cw(c2247.14,2752.86) 2247.14,2800 cw(c2247.14,2847.14) PPI2.4@2213.81,2813.81 ; v1@2269,2590 cw(c2269,2553.79) 2294.61,2579.39 cw(c2320.21,2605) v1@2284,2605 ; v1(2269,2605) 2416,2458 2467.19,2458 2534.72,2390.47 2989.53,2390.47 U1.6 ; v1@2383.39,2748.39 ccw(c2357.79,2722.79) 2357.79,2759 ccw(c2357.79,2795.21) v1@2383.39,2769.61 ; U1.6@3130.47,2230 ccw(c3083.33,2230) 3116.66,2263.34 ccw(c3150,2296.67) U1.6@3150,2249.53
NetPPI2_5: PPI2.5 U2.6 | length 1205.8
  Bottom Layer w20: PPI2.5@2199.72,2700.38 cw(c2218.68,2674.56) 2241.33,2697.21 ; PPI2.5@2199.87,2700.45 cw(c2214.17,2649.45) 2251.63,2686.91 ; PPI2.5 2238.54,2700 ; PPI2.5@2211.56,2684.26 cw(c2232.63,2655.56) 2257.8,2680.73 ; PPI2.5@2215.75,2688.45 cw(c2238.53,2671.74) 2238.53,2700 ; PPI2.5@2215.75,2711.55 ccw(c2238.53,2728.26) 2238.53,2700 ; U2.6@3030.47,2630 ccw(c2983.33,2630) 3016.66,2663.34 ccw(c3050,2696.67) U2.6@3050,2649.53 ; U2.6 2940.47,2739.53 2655,2739.53 2597.47,2682 2256.54,2682 2238.54,2700
NetPPI2_7: PPI2.7 RVCC.2 | length 651.9
  Top Layer w20: PPI2.7 2265,2500 2314,2549 2314,2614 2355.12,2655.12 ; PPI2.7@2213.81,2486.19 cw(c2247.14,2452.86) 2247.14,2500 cw(c2247.14,2547.14) PPI2.7@2213.81,2513.81 ; 2326.06,2626.06 cw(c2392.74,2559.39) RVCC.2@2396.01,2653.62 ; 2334.65,2634.65 cw(c2360.78,2608.51) RVCC.2@2383.09,2637.98 ; 2350.88,2650.88 cw(c2374.77,2626.99) RVCC.2@2395.16,2653.93 ; 2358.6,2658.6 cw(c2394.92,2622.27) RVCC.2@2396.71,2673.61 ; RVCC.2@2378.37,2642.91 ccw(c2355.12,2626.87) 2355.12,2655.12 ; RVCC.2@2378.37,2667.32 cw(c2355.12,2683.36) 2355.12,2655.12 ; RVCC.2 2355.12,2655.12
VCC: BT01.2 BT02.2 BT03.2 BT04.2 PL.11 PPI2.9 PUSB.1 U1.16 U2.16 | length 5581.8
  Top Layer w20: PUSB.1 2150,2050 2150,2250 PPI2.9 ; PUSB.1@2100,2019.53 ccw(c2100,2066.67) 2133.34,2033.34 ccw(c2166.67,2000) PUSB.1@2119.53,2000 ; PPI2.9@2180.47,2300 cw(c2133.33,2300) 2166.66,2266.66 cw(c2200,2233.33) PPI2.9@2200,2280.47 ; U2.16@2536.19,2916.19 cw(c2502.86,2882.86) 2550,2882.86 cw(c2597.14,2882.86) U2.16@2563.81,2916.19 ; U2.16 2550,2800 2600,2750 2600,2580 U1.16 ; v1@3676,2371 cw(c3639.79,2371) 3665.39,2345.39 cw(c3691,2319.79) v1@3691,2356 ; PL.11@3686.19,1813.81 ccw(c3652.86,1847.14) 3700,1847.14 ccw(c3747.14,1847.14) PL.11@3713.81,1813.81 ; BT01.2@3686.19,1886.19 cw(c3652.86,1852.86) 3700,1852.86 cw(c3747.14,1852.86) BT01.2@3713.81,1886.19 ; BT01.2@3686.19,1913.81 ccw(c3652.86,1947.14) 3700,1947.14 ccw(c3747.14,1947.14) BT01.2@3713.81,1913.81 ; BT02.2@3686.19,1986.19 cw(c3652.86,1952.86) 3700,1952.86 cw(c3747.14,1952.86) BT02.2@3713.81,1986.19 ; BT02.2@3686.19,2013.81 ccw(c3652.86,2047.14) 3700,2047.14 ccw(c3747.14,2047.14) BT02.2@3713.81,2013.81 ; BT03.2@3686.19,2086.19 cw(c3652.86,2052.86) 3700,2052.86 cw(c3747.14,2052.86) BT03.2@3713.81,2086.19 ; BT03.2@3686.19,2113.81 ccw(c3652.86,2147.14) 3700,2147.14 ccw(c3747.14,2147.14) BT03.2@3713.81,2113.81 ; v1(3691,2371) 3643.58,2323.58 3643.58,2259.42 3700,2203 BT03.2 BT02.2 BT01.2 PL.11
  Bottom Layer w20: PUSB.1@2100,1980.47 cw(c2100,1933.33) 2133.34,1966.66 cw(c2166.67,2000) PUSB.1@2119.53,2000 ; PUSB.1 2166,1934 2834,1934 BT04.2 2950,1950 3122,1950 3300,2128 3300,2310.47 3350,2360.47 ; U1.16@2635.52,2516.9 ccw(c2606,2490.2) 2606,2530 ; U1.16@2635.52,2543.1 cw(c2606,2569.8) 2606,2530 ; U1.16 2606,2530 ; BT04.2@2880.47,2000 cw(c2833.33,2000) 2866.66,1966.66 cw(c2900,1933.33) 2900,1980.47 cw(c2900,1933.33) 2933.34,1966.66 cw(c2966.67,2000) BT04.2@2919.53,2000 ; 3629.37,2360.47 ccw(c3629.37,2432.63) v1@3680.39,2381.61 ; v1(3691,2371) 3680.47,2360.47 3350,2360.47 ; 2606,2530 2599,2537 2525,2537 2509,2521 2509,2458.62 2547.14,2420.47 3050,2420.47 3110,2360.47 3350,2360.47
pads on no net: PPI2.6 PPI2.8 PUSB.2 PUSB.3 PUSB.4 U2.7 U2.9 U2.10 U2.11 U2.12 U2.13

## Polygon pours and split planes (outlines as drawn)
GND on Top Layer "Top Layer-No Net" (solid): 2000,3600 2000,1700 3890,1700 3890,3600 2000,3600
GND on Bottom Layer "Top Layer-No Net" (solid): 2000,3600 2000,1700 3890,1700 3890,3590 3880,3600 2000,3600

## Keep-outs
Keep-Out Layer:
  lines w10: 2000,1700 2000,3600 3890,3600 3890,1700 2000,1700

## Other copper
Bottom Layer:
  text "By Zhang Di" at 3250,2130 h60
  text "2018.11.04" at 3250,2060 h30

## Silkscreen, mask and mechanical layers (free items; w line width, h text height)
Mechanical 1:
  lines w10: 2000,1700 2000,3600 3890,3600 3890,1710 2010,1710 2000,1700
